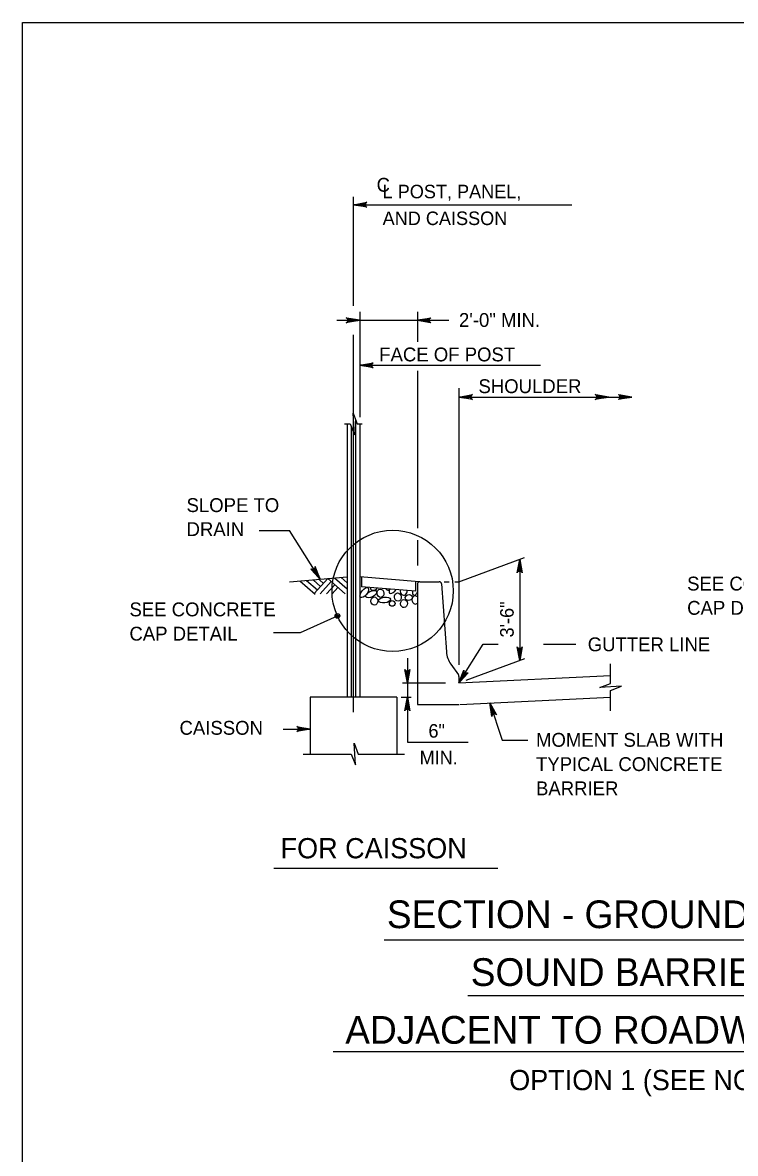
# Model space of a CAD drawing. Extents: x 3761 to 5458, y -616 to 1166.
# Drawn here: x 4642.3 to 4800.4, y 306.1 to 556.7 of the extents above; entities that cross this region are included whole.
import ezdxf

# ---------------------------------------------------------------- set-up
doc = ezdxf.new("R2010")
doc.units = 0
doc.layers.add('1', color=7, linetype='Continuous')
doc.layers.add('2', color=7, linetype='Continuous')

msp = doc.modelspace()

# ---------------------------------------------------------------- linework, layer by layer
at = {"layer": '1'}
for p, q in [((4715.7, 493.91), (4715.7, 518.08)), ((4715.7, 516.32), (4764.1, 516.32)), ((4717.08, 492.57), (4717.08, 469.27)), ((4729.88, 492.57), (4729.88, 485.97)), ((4711.98, 490.72), (4736.86, 490.72)), ((4715.7, 403.88), (4715.7, 487.52)), ((4717.08, 480.75), (4757.13, 480.75)), ((4729.88, 479.48), (4729.88, 444.61)), ((4739.08, 475.68), (4739.08, 414.34)), ((4739.08, 473.7), (4777.41, 473.7)), ((4716.18, 468.68), (4716.18, 407.16)), ((4713.68, 467.75), (4714.94, 467.75)), ((4714.32, 467.75), (4714.32, 407.16)), ((4715.21, 467.08), (4715.21, 407.16)), ((4716.54, 467.75), (4717.59, 467.75)), ((4717.08, 467.75), (4717.08, 407.16)), ((4694.77, 444.14), (4701.54, 444.14)), ((4708.28, 433.33), (4701.54, 444.14)), ((4729.88, 442.01), (4729.88, 436.36)), ((4739.08, 432.76), (4753.65, 438.13)), ((4752.56, 437.73), (4752.56, 415.33)), ((4701.52, 432.76), (4714.32, 433.83)), ((4714.27, 431.11), (4711.48, 433.59)), ((4714.27, 432.53), (4712.98, 433.68)), ((4730.24, 432.73), (4717.08, 433.83)), ((4717.48, 433.8), (4717.48, 431.66)), ((4703.83, 432.97), (4707.18, 429.98)), ((4705.32, 433.06), (4707.7, 430.94)), ((4706.82, 433.15), (4708.41, 431.73)), ((4707, 430.15), (4709.99, 433.51)), ((4708.15, 433.16), (4709.02, 432.39)), ((4708.33, 430.06), (4710.78, 432.8)), ((4709.75, 430.06), (4711.57, 432.09)), ((4713.86, 430.06), (4709.99, 433.51)), ((4710.95, 430.06), (4712.25, 431.51)), ((4729.48, 430.66), (4717.48, 431.66)), ((4729.48, 432.8), (4729.48, 430.66)), ((4729.88, 432.23), (4729.88, 405.56)), ((4730.41, 432.76), (4734.72, 432.76)), ((4735.25, 432.27), (4736.31, 417.2)), ((4735.79, 432.76), (4736.93, 432.76)), ((4738.18, 432.76), (4739.08, 432.76)), ((4703.99, 421.49), (4712.14, 425.19)), ((4697.99, 421.49), (4703.99, 421.49)), ((4739.08, 410.36), (4744.43, 418.94)), ((4744.43, 418.94), (4747.79, 418.94)), ((4757.85, 418.94), (4765.01, 418.94)), ((4727.64, 415.84), (4727.64, 397.2)), ((4737.29, 414.47), (4738.98, 412.1)), ((4740.67, 410.95), (4753.69, 415.74)), ((4772.69, 410.24), (4772.69, 414.59)), ((4739.08, 410.36), (4772.69, 411.99)), ((4739.08, 411.79), (4739.08, 410.36)), ((4726.55, 410.36), (4736.13, 410.36)), ((4772.69, 404.13), (4772.69, 408.64)), ((4706.1, 407.16), (4706.1, 394.57)), ((4725.3, 407.16), (4706.1, 407.16)), ((4725.3, 407.16), (4725.3, 394.57)), ((4726.25, 407.16), (4728.52, 407.16)), ((4739.31, 405.58), (4772.69, 407.19)), ((4729.88, 405.56), (4739.08, 405.56)), ((4745.93, 405.9), (4748.69, 397.66)), ((4700.1, 400.11), (4706.1, 400.11)), ((4727.64, 397.2), (4741.12, 397.2)), ((4748.69, 397.66), (4754.35, 397.66)), ((4704.54, 394.57), (4715.16, 394.57)), ((4716.76, 394.57), (4726.99, 394.57)), ((4698.05, 369.28), (4747.71, 369.28)), ((4722.53, 353.42), (4868.22, 353.42)), ((4741.09, 341.04), (4849.84, 341.04)), ((4711.22, 328.65), (4880.17, 328.65))]:
    msp.add_line(p, q, dxfattribs=at)
for points in [[(4715.7, 516.32), (4718.68, 516.88), (4718.45, 516.72), (4718.33, 516.52), (4718.3, 516.32), (4718.33, 516.12), (4718.45, 515.92), (4718.68, 515.76), (4715.7, 516.32), (4718.45, 515.92), (4718.33, 516.12), (4715.7, 516.32), (4718.3, 516.32), (4718.33, 516.52), (4715.7, 516.32), (4718.45, 516.72)], [(4717.08, 490.72), (4714.1, 490.16), (4714.21, 490.24), (4714.33, 490.32), (4714.39, 490.42), (4714.45, 490.52), (4714.46, 490.62), (4714.48, 490.72), (4714.46, 490.82), (4714.45, 490.92), (4714.39, 491.02), (4714.33, 491.12), (4714.21, 491.2), (4714.1, 491.28), (4717.08, 490.72), (4714.21, 491.2), (4714.33, 491.12), (4717.08, 490.72), (4714.39, 491.02), (4714.45, 490.92), (4717.08, 490.72), (4714.46, 490.82), (4714.48, 490.72), (4717.08, 490.72), (4714.46, 490.62), (4714.45, 490.52), (4717.08, 490.72), (4714.39, 490.42), (4714.33, 490.32), (4717.08, 490.72), (4714.21, 490.24)], [(4729.88, 490.72), (4732.86, 491.28), (4732.75, 491.2), (4732.63, 491.12), (4732.57, 491.02), (4732.51, 490.92), (4732.5, 490.82), (4732.48, 490.72), (4732.5, 490.62), (4732.51, 490.52), (4732.57, 490.42), (4732.63, 490.32), (4732.75, 490.24), (4732.86, 490.16), (4729.88, 490.72), (4732.75, 490.24), (4732.63, 490.32), (4729.88, 490.72), (4732.57, 490.42), (4732.51, 490.52), (4729.88, 490.72), (4732.5, 490.62), (4732.48, 490.72), (4729.88, 490.72), (4732.5, 490.82), (4732.51, 490.92), (4729.88, 490.72), (4732.57, 491.02), (4732.63, 491.12), (4729.88, 490.72), (4732.75, 491.2)], [(4717.08, 480.75), (4720.06, 481.31), (4719.83, 481.15), (4719.71, 480.95), (4719.68, 480.75), (4719.71, 480.55), (4719.83, 480.35), (4720.06, 480.19), (4717.08, 480.75), (4719.83, 480.35), (4719.71, 480.55), (4717.08, 480.75), (4719.68, 480.75), (4719.71, 480.95), (4717.08, 480.75), (4719.83, 481.15)], [(4739.08, 473.7), (4742.06, 474.26), (4741.83, 474.1), (4741.71, 473.9), (4741.68, 473.7), (4741.71, 473.5), (4741.83, 473.3), (4742.06, 473.14), (4739.08, 473.7), (4741.83, 473.3), (4741.71, 473.5), (4739.08, 473.7), (4741.68, 473.7), (4741.71, 473.9), (4739.08, 473.7), (4741.83, 474.1)], [(4772.29, 473.7), (4769.31, 473.14), (4769.42, 473.22), (4769.54, 473.3), (4769.6, 473.4), (4769.65, 473.5), (4769.67, 473.6), (4769.69, 473.7), (4769.67, 473.8), (4769.65, 473.9), (4769.6, 474), (4769.54, 474.1), (4769.42, 474.18), (4769.31, 474.26), (4772.29, 473.7), (4769.42, 474.18), (4769.54, 474.1), (4772.29, 473.7), (4769.6, 474), (4769.65, 473.9), (4772.29, 473.7), (4769.67, 473.8), (4769.69, 473.7), (4772.29, 473.7), (4769.67, 473.6), (4769.65, 473.5), (4772.29, 473.7), (4769.6, 473.4), (4769.54, 473.3), (4772.29, 473.7), (4769.42, 473.22)], [(4777.41, 473.7), (4774.43, 473.14), (4774.54, 473.22), (4774.66, 473.3), (4774.72, 473.4), (4774.77, 473.5), (4774.79, 473.6), (4774.81, 473.7), (4774.79, 473.8), (4774.77, 473.9), (4774.72, 474), (4774.66, 474.1), (4774.54, 474.18), (4774.43, 474.26), (4777.41, 473.7), (4774.54, 474.18), (4774.66, 474.1), (4777.41, 473.7), (4774.72, 474), (4774.77, 473.9), (4777.41, 473.7), (4774.79, 473.8), (4774.81, 473.7), (4777.41, 473.7), (4774.79, 473.6), (4774.77, 473.5), (4777.41, 473.7), (4774.72, 473.4), (4774.66, 473.3), (4777.41, 473.7), (4774.54, 473.22)], [(4714.94, 467.75), (4715.92, 465.35), (4715.62, 470.15), (4716.54, 467.75)], [(4708.28, 433.33), (4707.19, 436.16), (4707.18, 436.02), (4707.17, 435.88), (4707.12, 435.78), (4707.07, 435.67), (4706.99, 435.61), (4706.91, 435.54), (4706.82, 435.5), (4706.73, 435.46), (4706.61, 435.46), (4706.49, 435.46), (4706.37, 435.52), (4706.24, 435.57), (4708.28, 433.33), (4706.37, 435.52), (4706.49, 435.46), (4708.28, 433.33), (4706.61, 435.46), (4706.73, 435.46), (4708.28, 433.33), (4706.82, 435.5), (4706.91, 435.54), (4708.28, 433.33), (4706.99, 435.61), (4707.07, 435.67), (4708.28, 433.33), (4707.12, 435.78), (4707.17, 435.88), (4708.28, 433.33), (4707.18, 436.02)], [(4752.56, 437.73), (4753.12, 434.75), (4753.04, 434.86), (4752.96, 434.98), (4752.86, 435.03), (4752.76, 435.09), (4752.66, 435.11), (4752.56, 435.13), (4752.46, 435.11), (4752.36, 435.09), (4752.26, 435.03), (4752.16, 434.98), (4752.08, 434.86), (4752, 434.75), (4752.56, 437.73), (4752.08, 434.86), (4752.16, 434.98), (4752.56, 437.73), (4752.26, 435.03), (4752.36, 435.09), (4752.56, 437.73), (4752.46, 435.11), (4752.56, 435.13), (4752.56, 437.73), (4752.66, 435.11), (4752.76, 435.09), (4752.56, 437.73), (4752.86, 435.03), (4752.96, 434.98), (4752.56, 437.73), (4753.04, 434.86)], [(4752.56, 415.33), (4752, 418.31), (4752.08, 418.2), (4752.16, 418.08), (4752.26, 418.02), (4752.36, 417.96), (4752.46, 417.95), (4752.56, 417.93), (4752.66, 417.95), (4752.76, 417.96), (4752.86, 418.02), (4752.96, 418.08), (4753.04, 418.2), (4753.12, 418.31), (4752.56, 415.33), (4753.04, 418.2), (4752.96, 418.08), (4752.56, 415.33), (4752.86, 418.02), (4752.76, 417.96), (4752.56, 415.33), (4752.66, 417.95), (4752.56, 417.93), (4752.56, 415.33), (4752.46, 417.95), (4752.36, 417.96), (4752.56, 415.33), (4752.26, 418.02), (4752.16, 418.08), (4752.56, 415.33), (4752.08, 418.2)], [(4727.64, 410.36), (4727.08, 413.35), (4727.16, 413.23), (4727.24, 413.12), (4727.34, 413.06), (4727.44, 413), (4727.54, 412.98), (4727.64, 412.96), (4727.74, 412.98), (4727.84, 413), (4727.94, 413.06), (4728.04, 413.12), (4728.12, 413.23), (4728.2, 413.35), (4727.64, 410.36), (4728.12, 413.23), (4728.04, 413.12), (4727.64, 410.36), (4727.94, 413.06), (4727.84, 413), (4727.64, 410.36), (4727.74, 412.98), (4727.64, 412.96), (4727.64, 410.36), (4727.54, 412.98), (4727.44, 413), (4727.64, 410.36), (4727.34, 413.06), (4727.24, 413.12), (4727.64, 410.36), (4727.16, 413.23)], [(4739.08, 410.36), (4740.17, 413.2), (4740.18, 413.06), (4740.19, 412.92), (4740.24, 412.81), (4740.29, 412.71), (4740.37, 412.64), (4740.45, 412.58), (4740.54, 412.54), (4740.64, 412.5), (4740.75, 412.5), (4740.87, 412.5), (4741, 412.55), (4741.12, 412.61), (4739.08, 410.36), (4741, 412.55), (4740.87, 412.5), (4739.08, 410.36), (4740.75, 412.5), (4740.64, 412.5), (4739.08, 410.36), (4740.54, 412.54), (4740.45, 412.58), (4739.08, 410.36), (4740.37, 412.64), (4740.29, 412.71), (4739.08, 410.36), (4740.24, 412.81), (4740.19, 412.92), (4739.08, 410.36), (4740.18, 413.06)], [(4772.69, 408.64), (4775.09, 409.62), (4770.29, 409.33), (4772.69, 410.24)], [(4727.64, 407.16), (4728.2, 404.18), (4728.12, 404.3), (4728.04, 404.41), (4727.94, 404.47), (4727.84, 404.53), (4727.74, 404.55), (4727.64, 404.56), (4727.54, 404.55), (4727.44, 404.53), (4727.34, 404.47), (4727.24, 404.41), (4727.16, 404.3), (4727.08, 404.18), (4727.64, 407.16), (4727.16, 404.3), (4727.24, 404.41), (4727.64, 407.16), (4727.34, 404.47), (4727.44, 404.53), (4727.64, 407.16), (4727.54, 404.55), (4727.64, 404.56), (4727.64, 407.16), (4727.74, 404.55), (4727.84, 404.53), (4727.64, 407.16), (4727.94, 404.47), (4728.04, 404.41), (4727.64, 407.16), (4728.12, 404.3)], [(4745.93, 405.9), (4747.44, 403.26), (4747.21, 403.43), (4746.98, 403.47), (4746.78, 403.44), (4746.6, 403.34), (4746.46, 403.17), (4746.38, 402.9), (4745.93, 405.9), (4746.46, 403.17), (4746.6, 403.34), (4745.93, 405.9), (4746.78, 403.44), (4746.98, 403.47), (4745.93, 405.9), (4747.21, 403.43)], [(4706.1, 400.11), (4703.11, 399.6), (4703.34, 399.75), (4703.46, 399.95), (4703.5, 400.15), (4703.47, 400.35), (4703.35, 400.55), (4703.12, 400.71), (4706.1, 400.11), (4703.35, 400.55), (4703.47, 400.35), (4706.1, 400.11), (4703.5, 400.15), (4703.46, 399.95), (4706.1, 400.11), (4703.34, 399.75)], [(4715.16, 394.57), (4716.13, 392.17), (4715.84, 396.97), (4716.76, 394.57)]]:
    msp.add_lwpolyline(points, dxfattribs=at)
for centre, radius in [((4724.38, 430.74), 13.44), ((4712.14, 425.19), 0.533), ((4712.14, 425.19), 0.267)]:
    msp.add_circle(centre, radius, dxfattribs=at)
for centre, radius, start, end in [((4730.41, 432.23), 0.533, 90, 180), ((4734.72, 432.23), 0.533, 4.0219, 90), ((4741.63, 417.57), 5.33, 184.0219, 215.5414), ((4738.55, 411.79), 0.533, 0, 35.5414)]:
    msp.add_arc(centre, radius, start, end, dxfattribs=at)
for centre, major_axis, ratio in [((4718.1, 430.36), (-0.83, -1.05), 0.479042), ((4721.69, 430.21), (-0.053, 0.902), 0.844245), ((4719.64, 430.02), (-1.19, -0.6), 0.479042), ((4720.32, 428.49), (-0.053, 0.902), 0.844245), ((4722.58, 428.71), (-1.33, -0.16), 0.479042), ((4724.29, 427.95), (-0.451, 0.451), 0.982495), ((4725.54, 429.37), (-0.053, 0.902), 0.844245), ((4726.91, 427.93), (-0.053, 0.902), 0.844245), ((4727.97, 429.26), (0.767, 0.247), 0.796199)]:
    msp.add_ellipse(centre, major_axis=major_axis, ratio=ratio, dxfattribs=at)
for centre, major_axis, ratio, start_param, end_param in [((4720.27, 431.5), (0.788, 0.377), 0.646802, 2.514027, 5.440341), ((4723.24, 432.2), (0.16, -1.33), 0.479042, 5.504237, 6.86597), ((4724.55, 431.28), (-0.83, -1.05), 0.479042, 5.203222, 7.974892), ((4726.83, 430.68), (-0.053, 0.902), 0.844245, 1.226507, 4.816703), ((4729.43, 428.73), (-0.053, 0.902), 0.844245, 5.577625, 9.99132), ((4729.33, 430.57), (0.279, 0.738), 0.687276, 1.636821, 4.886434)]:
    msp.add_ellipse(centre, major_axis=major_axis, ratio=ratio, start_param=start_param, end_param=end_param, dxfattribs=at)
at = {"layer": '2'}
for p, q in [((4642.34, -7.31), (4642.34, 556.69)), ((4642.34, 556.69), (5428.34, 556.69))]:
    msp.add_line(p, q, dxfattribs=at)

# ---------------------------------------------------------------- texts
at = {"layer": '1'}
for s, height, p in [('C', 3.07, (4720.83, 519.21)), ('L POST, PANEL,', 3, (4722.16, 517.75)), ('AND CAISSON', 3, (4722.16, 511.82)), ('2\'-0" MIN.', 3.072, (4739.09, 489.24)), ('FACE OF POST', 3.0721, (4721.41, 481.61)), ('SHOULDER', 3.072, (4743.41, 474.57)), ('SLOPE TO', 3.072, (4678.69, 448.21)), ('DRAIN', 3.072, (4678.69, 442.89)), ('SEE CONCRETE', 3.0721, (4789.68, 430.82)), ('SEE CONCRETE', 3.0721, (4666.03, 425.1)), ('CAP DETAIL', 3.072, (4789.68, 425.44)), ('CAP DETAIL', 3.072, (4666.03, 419.72)), ('GUTTER LINE', 3.0721, (4767.64, 417.35)), ('CAISSON', 3.072, (4677.13, 398.85)), ('6"', 3, (4732.32, 398.21)), ('MOMENT SLAB WITH', 3.0721, (4756.17, 396.19)), ('MIN.', 3, (4730.36, 392.29)), ('TYPICAL CONCRETE', 3.0721, (4756.17, 390.81)), ('BARRIER', 3.072, (4756.17, 385.44)), ('FOR CAISSON', 4.48, (4699.54, 371.47)), ('SECTION - GROUND MOUNTED', 6.1439, (4723.1, 355.99)), ('SOUND BARRIER WALL', 6.1439, (4741.7, 343.18)), ('ADJACENT TO ROADWAY BARRIER', 6.1439, (4713.88, 330.37)), ('OPTION 1 (SEE NOTE 2)', 4.48, (4750.22, 320.08))]:
    msp.add_text(s, height=height, dxfattribs=at).set_placement(p)
msp.add_text('3\'-6"', height=3, rotation=90, dxfattribs=at).set_placement((4751.22, 420.41))

doc.saveas('drawing.dxf')
